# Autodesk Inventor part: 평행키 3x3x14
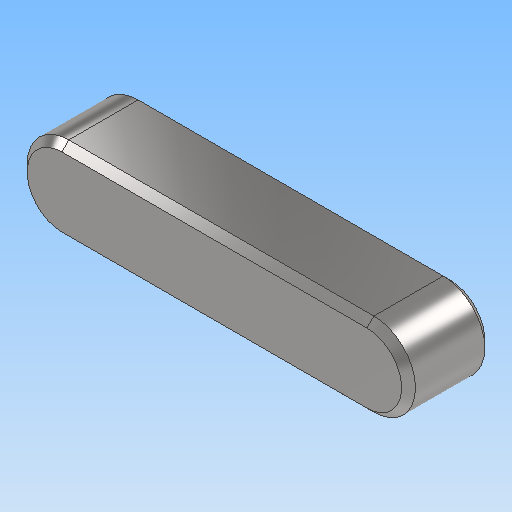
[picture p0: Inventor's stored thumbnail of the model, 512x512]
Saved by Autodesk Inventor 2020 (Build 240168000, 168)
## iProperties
Created: 2024-09
Part Number: 평행키 3x3x14
Material: 강철, 연강
Description: 키 및 해당 키홈
Document SubType Name: Modeling
Designer: oem
Density: 7.85 g/cm^3
Appearance: 기본값
Author: jhkim
Sending System: Autodesk Inventor 2025
Preprocessor: ST-DEVELOPER v20
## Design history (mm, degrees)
feature "Solid1"
node "솔리드1"
